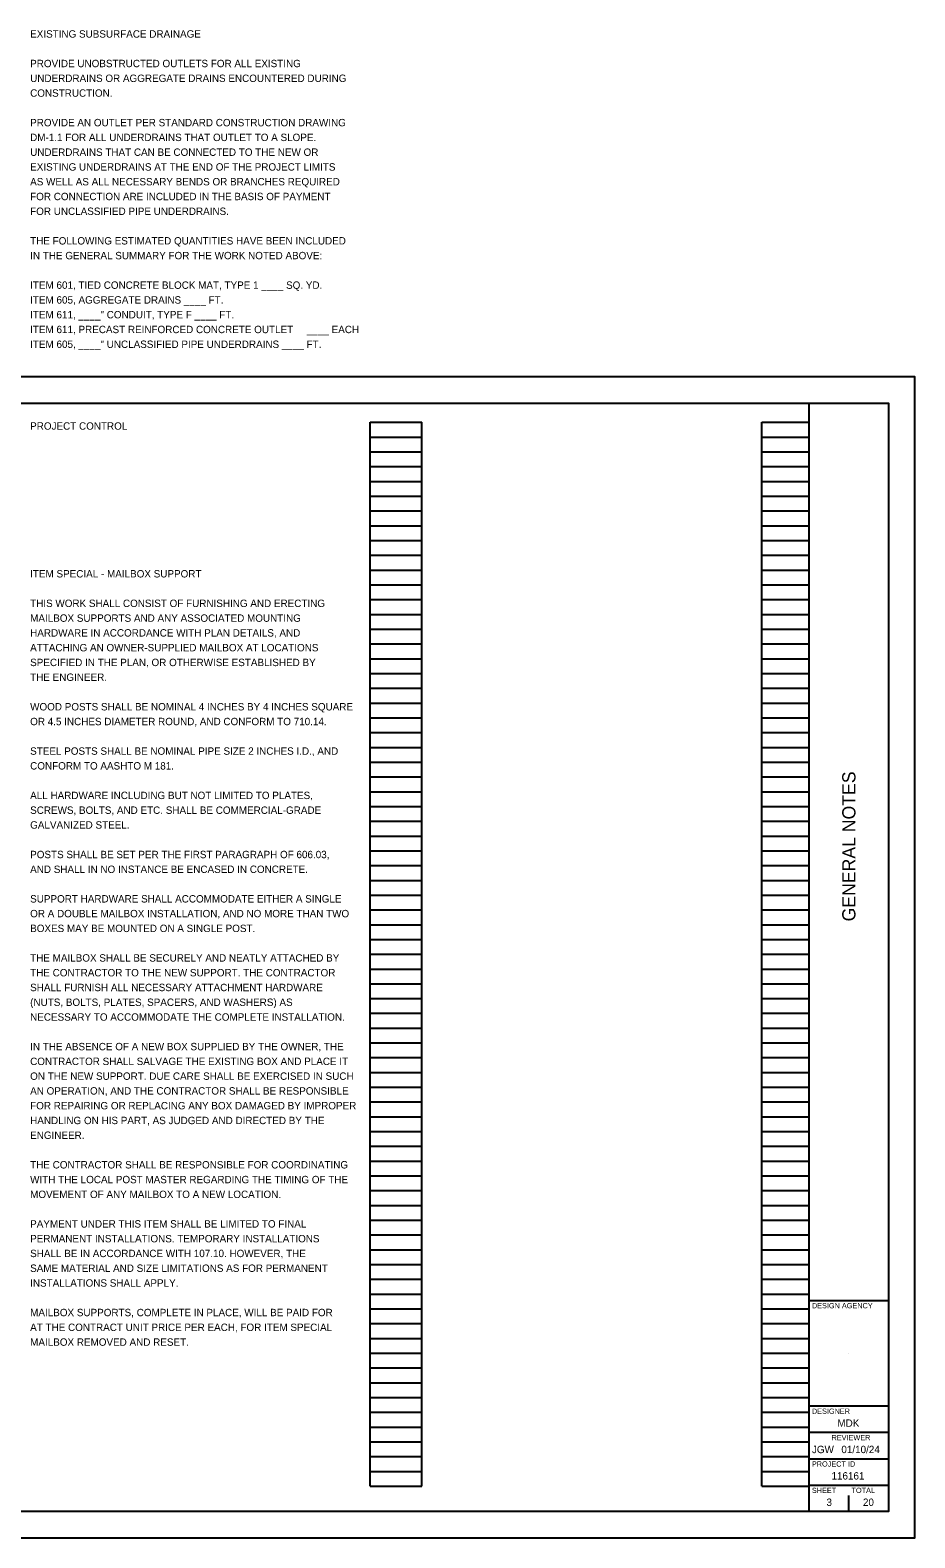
# Model space of a CAD drawing. Extents: x 0 to 34, y 0 to 28.6.
# Drawn here: x 17.24 to 34, y 0 to 28.57 of the extents above; entities that cross this region are included whole.
import ezdxf

# ---------------------------------------------------------------- set-up
doc = ezdxf.new("R2010")
doc.units = 0
for name, color, linetype in [('SH_Border', 7, 'Continuous'), ('SH_Data', 7, 'Continuous'), ('SH_Text', 7, 'Continuous')]:
    doc.layers.add(name, color=color, linetype=linetype)

msp = doc.modelspace()

# ---------------------------------------------------------------- linework, layer by layer
at = {"layer": 'SH_Border'}
for p, q in [((32, 0.5), (32, 21.5)), ((32, 4.5), (33.5, 4.5)), ((32, 2.5), (33.5, 2.5)), ((32, 2), (33.5, 2)), ((32, 1.5), (33.5, 1.5)), ((32, 1), (33.5, 1))]:
    msp.add_line(p, q, dxfattribs=at)
msp.add_lwpolyline([(1.5, 21.5), (33.5, 21.5), (33.5, 0.5), (1.5, 0.5)], close=True, dxfattribs=at)
at = {"layer": 'SH_Data'}
for p, q in [((23.68, 0.98), (23.68, 21.14)), ((23.68, 21.14), (24.66, 21.14)), ((23.68, 20.86), (24.66, 20.86)), ((24.66, 0.98), (24.66, 21.14)), ((31.1, 0.98), (31.1, 21.14)), ((31.1, 21.14), (32, 21.14)), ((31.1, 20.86), (32, 20.86)), ((32, 0.98), (32, 21.14)), ((23.68, 20.58), (24.66, 20.58)), ((31.1, 20.58), (32, 20.58)), ((23.68, 20.3), (24.66, 20.3)), ((31.1, 20.3), (32, 20.3)), ((23.68, 20.02), (24.66, 20.02)), ((31.1, 20.02), (32, 20.02)), ((23.68, 19.74), (24.66, 19.74)), ((31.1, 19.74), (32, 19.74)), ((23.68, 19.46), (24.66, 19.46)), ((31.1, 19.46), (32, 19.46)), ((23.68, 19.18), (24.66, 19.18)), ((31.1, 19.18), (32, 19.18)), ((23.68, 18.9), (24.66, 18.9)), ((31.1, 18.9), (32, 18.9)), ((23.68, 18.62), (24.66, 18.62)), ((31.1, 18.62), (32, 18.62)), ((23.68, 18.34), (24.66, 18.34)), ((31.1, 18.34), (32, 18.34)), ((23.68, 18.06), (24.66, 18.06)), ((31.1, 18.06), (32, 18.06)), ((23.68, 17.78), (24.66, 17.78)), ((31.1, 17.78), (32, 17.78)), ((23.68, 17.5), (24.66, 17.5)), ((31.1, 17.5), (32, 17.5)), ((23.68, 17.22), (24.66, 17.22)), ((31.1, 17.22), (32, 17.22)), ((23.68, 16.94), (24.66, 16.94)), ((31.1, 16.94), (32, 16.94)), ((23.68, 16.66), (24.66, 16.66)), ((31.1, 16.66), (32, 16.66)), ((23.68, 16.38), (24.66, 16.38)), ((31.1, 16.38), (32, 16.38)), ((23.68, 16.1), (24.66, 16.1)), ((31.1, 16.1), (32, 16.1)), ((23.68, 15.82), (24.66, 15.82)), ((31.1, 15.82), (32, 15.82)), ((23.68, 15.54), (24.66, 15.54)), ((31.1, 15.54), (32, 15.54)), ((23.68, 15.26), (24.66, 15.26)), ((31.1, 15.26), (32, 15.26)), ((23.68, 14.98), (24.66, 14.98)), ((31.1, 14.98), (32, 14.98)), ((23.68, 14.7), (24.66, 14.7)), ((31.1, 14.7), (32, 14.7)), ((23.68, 14.42), (24.66, 14.42)), ((31.1, 14.42), (32, 14.42)), ((23.68, 14.14), (24.66, 14.14)), ((31.1, 14.14), (32, 14.14)), ((23.68, 13.86), (24.66, 13.86)), ((31.1, 13.86), (32, 13.86)), ((23.68, 13.58), (24.66, 13.58)), ((31.1, 13.58), (32, 13.58)), ((23.68, 13.3), (24.66, 13.3)), ((31.1, 13.3), (32, 13.3)), ((23.68, 13.02), (24.66, 13.02)), ((31.1, 13.02), (32, 13.02)), ((23.68, 12.74), (24.66, 12.74)), ((31.1, 12.74), (32, 12.74)), ((23.68, 12.46), (24.66, 12.46)), ((31.1, 12.46), (32, 12.46)), ((23.68, 12.18), (24.66, 12.18)), ((31.1, 12.18), (32, 12.18)), ((23.68, 11.9), (24.66, 11.9)), ((31.1, 11.9), (32, 11.9)), ((23.68, 11.62), (24.66, 11.62)), ((31.1, 11.62), (32, 11.62)), ((23.68, 11.34), (24.66, 11.34)), ((31.1, 11.34), (32, 11.34)), ((23.68, 11.06), (24.66, 11.06)), ((31.1, 11.06), (32, 11.06)), ((23.68, 10.78), (24.66, 10.78)), ((31.1, 10.78), (32, 10.78)), ((23.68, 10.5), (24.66, 10.5)), ((31.1, 10.5), (32, 10.5)), ((23.68, 10.22), (24.66, 10.22)), ((31.1, 10.22), (32, 10.22)), ((23.68, 9.94), (24.66, 9.94)), ((31.1, 9.94), (32, 9.94)), ((23.68, 9.66), (24.66, 9.66)), ((31.1, 9.66), (32, 9.66)), ((23.68, 9.38), (24.66, 9.38)), ((31.1, 9.38), (32, 9.38)), ((23.68, 9.1), (24.66, 9.1)), ((31.1, 9.1), (32, 9.1)), ((23.68, 8.82), (24.66, 8.82)), ((31.1, 8.82), (32, 8.82)), ((23.68, 8.54), (24.66, 8.54)), ((31.1, 8.54), (32, 8.54)), ((23.68, 8.26), (24.66, 8.26)), ((31.1, 8.26), (32, 8.26)), ((23.68, 7.98), (24.66, 7.98)), ((31.1, 7.98), (32, 7.98)), ((23.68, 7.7), (24.66, 7.7)), ((31.1, 7.7), (32, 7.7)), ((23.68, 7.42), (24.66, 7.42)), ((31.1, 7.42), (32, 7.42)), ((23.68, 7.14), (24.66, 7.14)), ((23.68, 6.86), (24.66, 6.86)), ((31.1, 7.14), (32, 7.14)), ((31.1, 6.86), (32, 6.86)), ((23.68, 6.58), (24.66, 6.58)), ((31.1, 6.58), (32, 6.58)), ((23.68, 6.3), (24.66, 6.3)), ((31.1, 6.3), (32, 6.3)), ((23.68, 6.02), (24.66, 6.02)), ((31.1, 6.02), (32, 6.02)), ((23.68, 5.74), (24.66, 5.74)), ((31.1, 5.74), (32, 5.74)), ((23.68, 5.46), (24.66, 5.46)), ((31.1, 5.46), (32, 5.46)), ((23.68, 5.18), (24.66, 5.18)), ((31.1, 5.18), (32, 5.18)), ((23.68, 4.9), (24.66, 4.9)), ((31.1, 4.9), (32, 4.9)), ((23.68, 4.62), (24.66, 4.62)), ((31.1, 4.62), (32, 4.62)), ((23.68, 4.34), (24.66, 4.34)), ((31.1, 4.34), (32, 4.34)), ((23.68, 4.06), (24.66, 4.06)), ((31.1, 4.06), (32, 4.06)), ((23.68, 3.78), (24.66, 3.78)), ((31.1, 3.78), (32, 3.78)), ((23.68, 3.5), (24.66, 3.5)), ((31.1, 3.5), (32, 3.5)), ((32.75, 3.5), (32.75, 3.5)), ((23.68, 3.22), (24.66, 3.22)), ((31.1, 3.22), (32, 3.22)), ((23.68, 2.94), (24.66, 2.94)), ((31.1, 2.94), (32, 2.94)), ((23.68, 2.66), (24.66, 2.66)), ((31.1, 2.66), (32, 2.66)), ((23.68, 2.38), (24.66, 2.38)), ((31.1, 2.38), (32, 2.38)), ((23.68, 2.1), (24.66, 2.1)), ((31.1, 2.1), (32, 2.1)), ((23.68, 1.82), (24.66, 1.82)), ((31.1, 1.82), (32, 1.82)), ((23.68, 1.54), (24.66, 1.54)), ((31.1, 1.54), (32, 1.54)), ((23.68, 1.26), (24.66, 1.26)), ((31.1, 1.26), (32, 1.26)), ((23.68, 0.98), (24.66, 0.98)), ((31.1, 0.98), (32, 0.98)), ((32.375, 0.675), (32.375, 0.675)), ((32.75, 0.5), (32.75, 0.8))]:
    msp.add_line(p, q, dxfattribs=at)
msp.add_lwpolyline([(0, 0), (34, 0), (34, 22), (0, 22)], close=True, dxfattribs=at)

# ---------------------------------------------------------------- texts
msp.add_text('GENERAL NOTES', height=0.25, rotation=90, dxfattribs=at).set_placement((32.875, 11.682))
for s, height, p in [('DESIGN AGENCY', 0.1, (32.05, 4.35)), ('DESIGNER', 0.1, (32.05, 2.35)), ('MDK', 0.14, (32.533, 2.105)), ('JGW', 0.14, (32.051, 1.605)), ('REVIEWER', 0.1, (32.422, 1.85)), ('01/10/24', 0.14, (32.608, 1.605)), ('PROJECT ID', 0.1, (32.05, 1.35)), ('116161', 0.14, (32.421, 1.105)), ('SHEET', 0.1, (32.05, 0.85)), ('TOTAL', 0.1, (32.8, 0.85)), ('3', 0.14, (32.326, 0.605)), ('20', 0.14, (33.017, 0.605))]:
    msp.add_text(s, height=height, dxfattribs=at).set_placement(p)
at = {"layer": 'SH_Text'}
for s, p in [('EXISTING SUBSURFACE DRAINAGE', (17.24, 28.43)), ('PROVIDE UNOBSTRUCTED OUTLETS FOR ALL EXISTING', (17.24, 27.87)), ('UNDERDRAINS OR AGGREGATE DRAINS ENCOUNTERED DURING', (17.24, 27.59)), ('CONSTRUCTION.', (17.24, 27.31)), ('PROVIDE AN OUTLET PER STANDARD CONSTRUCTION DRAWING', (17.24, 26.75)), ('DM-1.1 FOR ALL UNDERDRAINS THAT OUTLET TO A SLOPE.', (17.24, 26.47)), ('UNDERDRAINS THAT CAN BE CONNECTED TO THE NEW OR', (17.24, 26.19)), ('EXISTING UNDERDRAINS AT THE END OF THE PROJECT LIMITS', (17.24, 25.91)), ('AS WELL AS ALL NECESSARY BENDS OR BRANCHES REQUIRED', (17.24, 25.63)), ('FOR CONNECTION ARE INCLUDED IN THE BASIS OF PAYMENT', (17.24, 25.35)), ('FOR UNCLASSIFIED PIPE UNDERDRAINS.', (17.24, 25.07)), ('THE FOLLOWING ESTIMATED QUANTITIES HAVE BEEN INCLUDED', (17.24, 24.51)), ('IN THE GENERAL SUMMARY FOR THE WORK NOTED ABOVE:', (17.24, 24.23)), ('ITEM 601, TIED CONCRETE BLOCK MAT, TYPE 1 ____ SQ. YD.', (17.24, 23.67)), ('ITEM 605, AGGREGATE DRAINS ____ FT.', (17.24, 23.39)), ('ITEM 611, ____" CONDUIT, TYPE F ____ FT.', (17.24, 23.11)), ('ITEM 611, PRECAST REINFORCED CONCRETE OUTLET     ____ EACH', (17.24, 22.83)), ('ITEM 605, ____" UNCLASSIFIED PIPE UNDERDRAINS ____ FT.', (17.24, 22.55)), ('PROJECT CONTROL', (17.24, 21)), ('ITEM SPECIAL - MAILBOX SUPPORT', (17.24, 18.2)), ('THIS WORK SHALL CONSIST OF FURNISHING AND ERECTING', (17.24, 17.64)), ('MAILBOX SUPPORTS AND ANY ASSOCIATED MOUNTING', (17.24, 17.36)), ('HARDWARE IN ACCORDANCE WITH PLAN DETAILS, AND', (17.24, 17.08)), ('ATTACHING AN OWNER-SUPPLIED MAILBOX AT LOCATIONS', (17.24, 16.8)), ('SPECIFIED IN THE PLAN, OR OTHERWISE ESTABLISHED BY', (17.24, 16.52)), ('THE ENGINEER.', (17.24, 16.24)), ('WOOD POSTS SHALL BE NOMINAL 4 INCHES BY 4 INCHES SQUARE', (17.24, 15.68)), ('OR 4.5 INCHES DIAMETER ROUND, AND CONFORM TO 710.14.', (17.24, 15.4)), ('STEEL POSTS SHALL BE NOMINAL PIPE SIZE 2 INCHES I.D., AND', (17.24, 14.84)), ('CONFORM TO AASHTO M 181.', (17.24, 14.56)), ('ALL HARDWARE INCLUDING BUT NOT LIMITED TO PLATES,', (17.24, 14)), ('SCREWS, BOLTS, AND ETC. SHALL BE COMMERCIAL-GRADE', (17.24, 13.72)), ('GALVANIZED STEEL.', (17.24, 13.44)), ('POSTS SHALL BE SET PER THE FIRST PARAGRAPH OF 606.03,', (17.24, 12.88)), ('AND SHALL IN NO INSTANCE BE ENCASED IN CONCRETE.', (17.24, 12.6)), ('SUPPORT HARDWARE SHALL ACCOMMODATE EITHER A SINGLE', (17.24, 12.04)), ('OR A DOUBLE MAILBOX INSTALLATION, AND NO MORE THAN TWO', (17.24, 11.76)), ('BOXES MAY BE MOUNTED ON A SINGLE POST.', (17.24, 11.48)), ('THE MAILBOX SHALL BE SECURELY AND NEATLY ATTACHED BY', (17.24, 10.92)), ('THE CONTRACTOR TO THE NEW SUPPORT. THE CONTRACTOR', (17.24, 10.64)), ('SHALL FURNISH ALL NECESSARY ATTACHMENT HARDWARE', (17.24, 10.36)), ('(NUTS, BOLTS, PLATES, SPACERS, AND WASHERS) AS', (17.24, 10.08)), ('NECESSARY TO ACCOMMODATE THE COMPLETE INSTALLATION.', (17.24, 9.8)), ('IN THE ABSENCE OF A NEW BOX SUPPLIED BY THE OWNER, THE', (17.24, 9.24)), ('CONTRACTOR SHALL SALVAGE THE EXISTING BOX AND PLACE IT', (17.24, 8.96)), ('ON THE NEW SUPPORT. DUE CARE SHALL BE EXERCISED IN SUCH', (17.24, 8.68)), ('AN OPERATION, AND THE CONTRACTOR SHALL BE RESPONSIBLE', (17.24, 8.4)), ('FOR REPAIRING OR REPLACING ANY BOX DAMAGED BY IMPROPER', (17.24, 8.12)), ('HANDLING ON HIS PART, AS JUDGED AND DIRECTED BY THE', (17.24, 7.84)), ('ENGINEER.', (17.24, 7.56)), ('WITH THE LOCAL POST MASTER REGARDING THE TIMING OF THE', (17.24, 6.72)), ('THE CONTRACTOR SHALL BE RESPONSIBLE FOR COORDINATING', (17.24, 7)), ('MOVEMENT OF ANY MAILBOX TO A NEW LOCATION.', (17.24, 6.44)), ('PAYMENT UNDER THIS ITEM SHALL BE LIMITED TO FINAL', (17.24, 5.88)), ('PERMANENT INSTALLATIONS. TEMPORARY INSTALLATIONS', (17.24, 5.6)), ('SHALL BE IN ACCORDANCE WITH 107.10. HOWEVER, THE', (17.24, 5.32)), ('SAME MATERIAL AND SIZE LIMITATIONS AS FOR PERMANENT', (17.24, 5.04)), ('INSTALLATIONS SHALL APPLY.', (17.24, 4.76)), ('MAILBOX SUPPORTS, COMPLETE IN PLACE, WILL BE PAID FOR', (17.24, 4.2)), ('AT THE CONTRACT UNIT PRICE PER EACH, FOR ITEM SPECIAL', (17.24, 3.92)), ('MAILBOX REMOVED AND RESET.', (17.24, 3.64))]:
    msp.add_text(s, height=0.14, dxfattribs=at).set_placement(p)

doc.saveas('drawing.dxf')
